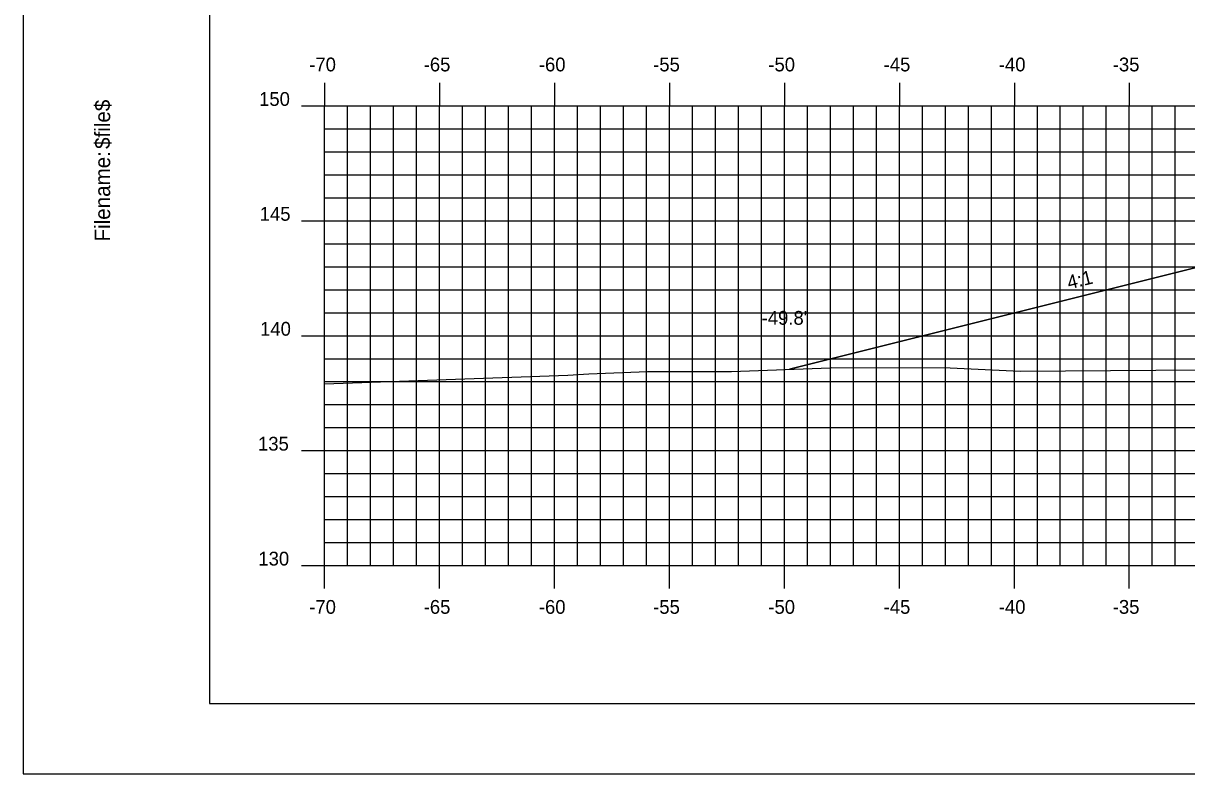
# Model space of a CAD drawing. Extents: x 851639 to 851810, y 365876 to 365986.
# Drawn here: x 851638.6 to 851689.2, y 365875.8 to 365908.4 of the extents above; entities that cross this region are included whole.
import ezdxf

# ---------------------------------------------------------------- set-up
doc = ezdxf.new("R2010")
doc.units = 0
for name, color, linetype in [('ANNOTATION', 7, 'Continuous'), ('BORDER', 7, 'Continuous'), ('D_Roadway_Centerline', 7, 'Continuous'), ('D_Roadway_SlopeLines', 7, 'Continuous'), ('D_Text_Standard', 7, 'Continuous'), ('H_V ANNOTATION', 7, 'Continuous'), ('MAJOR', 7, 'Continuous'), ('MINOR', 7, 'Continuous'), ('PLOT BOUNDARY', 7, 'Continuous'), ('S_Roadway_Centerline', 7, 'Continuous')]:
    doc.layers.add(name, color=color, linetype=linetype)

msp = doc.modelspace()

# ---------------------------------------------------------------- linework, layer by layer
at = {"layer": 'BORDER'}
msp.add_lwpolyline([(851646.655, 365878.833), (851806.655, 365878.833), (851806.655, 365983.833), (851646.655, 365983.833)], close=True, dxfattribs=at)
at = {"layer": 'D_Roadway_Centerline'}
msp.add_lwpolyline([(851671.874, 365893.373), (851687.655, 365897.318), (851697.655, 365899.818), (851721.655, 365898.522), (851731.655, 365896.022), (851745.471, 365892.568)], dxfattribs=at)
at = {"layer": 'D_Roadway_SlopeLines'}
msp.add_lwpolyline([(851697.655, 365899.818), (851687.655, 365897.318), (851671.874, 365893.373)], dxfattribs=at)
at = {"layer": 'MAJOR'}
for p, q in [((851651.655, 365905.835), (851651.655, 365904.833)), ((851656.655, 365905.835), (851656.655, 365904.833)), ((851661.655, 365905.835), (851661.655, 365904.833)), ((851666.655, 365905.835), (851666.655, 365904.833)), ((851671.655, 365905.835), (851671.655, 365904.833)), ((851676.655, 365905.835), (851676.655, 365904.833)), ((851681.655, 365905.835), (851681.655, 365904.833)), ((851686.655, 365905.835), (851686.655, 365904.833)), ((851650.653, 365904.833), (851651.655, 365904.833)), ((851651.655, 365904.833), (851791.655, 365904.833)), ((851651.655, 365884.833), (851651.655, 365904.833)), ((851651.655, 365884.833), (851651.655, 365904.833)), ((851651.655, 365904.833), (851791.655, 365904.833)), ((851656.655, 365884.833), (851656.655, 365904.833)), ((851661.655, 365884.833), (851661.655, 365904.833)), ((851666.655, 365884.833), (851666.655, 365904.833)), ((851671.655, 365884.833), (851671.655, 365904.833)), ((851676.655, 365884.833), (851676.655, 365904.833)), ((851681.655, 365884.833), (851681.655, 365904.833)), ((851686.655, 365884.833), (851686.655, 365904.833)), ((851650.653, 365899.833), (851651.655, 365899.833)), ((851651.655, 365899.833), (851791.655, 365899.833)), ((851650.653, 365894.833), (851651.655, 365894.833)), ((851651.655, 365894.833), (851791.655, 365894.833)), ((851650.653, 365889.833), (851651.655, 365889.833)), ((851651.655, 365889.833), (851791.655, 365889.833)), ((851650.653, 365884.833), (851651.655, 365884.833)), ((851651.655, 365884.833), (851791.655, 365884.833)), ((851651.655, 365884.833), (851791.655, 365884.833)), ((851651.655, 365883.831), (851651.655, 365884.833)), ((851656.655, 365883.831), (851656.655, 365884.833)), ((851661.655, 365883.831), (851661.655, 365884.833)), ((851666.655, 365883.831), (851666.655, 365884.833)), ((851671.655, 365883.831), (851671.655, 365884.833)), ((851676.655, 365883.831), (851676.655, 365884.833)), ((851681.655, 365883.831), (851681.655, 365884.833)), ((851686.655, 365883.831), (851686.655, 365884.833))]:
    msp.add_line(p, q, dxfattribs=at)
at = {"layer": 'MINOR'}
for p, q in [((851652.655, 365884.833), (851652.655, 365904.833)), ((851653.655, 365884.833), (851653.655, 365904.833)), ((851654.655, 365884.833), (851654.655, 365904.833)), ((851655.655, 365884.833), (851655.655, 365904.833)), ((851657.655, 365884.833), (851657.655, 365904.833)), ((851658.655, 365884.833), (851658.655, 365904.833)), ((851659.655, 365884.833), (851659.655, 365904.833)), ((851660.655, 365884.833), (851660.655, 365904.833)), ((851662.655, 365884.833), (851662.655, 365904.833)), ((851663.655, 365884.833), (851663.655, 365904.833)), ((851664.655, 365884.833), (851664.655, 365904.833)), ((851665.655, 365884.833), (851665.655, 365904.833)), ((851667.655, 365884.833), (851667.655, 365904.833)), ((851668.655, 365884.833), (851668.655, 365904.833)), ((851669.655, 365884.833), (851669.655, 365904.833)), ((851670.655, 365884.833), (851670.655, 365904.833)), ((851672.655, 365884.833), (851672.655, 365904.833)), ((851673.655, 365884.833), (851673.655, 365904.833)), ((851674.655, 365884.833), (851674.655, 365904.833)), ((851675.655, 365884.833), (851675.655, 365904.833)), ((851677.655, 365884.833), (851677.655, 365904.833)), ((851678.655, 365884.833), (851678.655, 365904.833)), ((851679.655, 365884.833), (851679.655, 365904.833)), ((851680.655, 365884.833), (851680.655, 365904.833)), ((851682.655, 365884.833), (851682.655, 365904.833)), ((851683.655, 365884.833), (851683.655, 365904.833)), ((851684.655, 365884.833), (851684.655, 365904.833)), ((851685.655, 365884.833), (851685.655, 365904.833)), ((851687.655, 365884.833), (851687.655, 365904.833)), ((851688.655, 365884.833), (851688.655, 365904.833)), ((851651.655, 365903.833), (851791.655, 365903.833)), ((851651.655, 365903.833), (851652.657, 365903.833)), ((851651.655, 365902.833), (851791.655, 365902.833)), ((851651.655, 365902.833), (851652.657, 365902.833)), ((851651.655, 365901.833), (851791.655, 365901.833)), ((851651.655, 365901.833), (851652.657, 365901.833)), ((851651.655, 365900.833), (851791.655, 365900.833)), ((851651.655, 365900.833), (851652.657, 365900.833)), ((851651.655, 365898.833), (851791.655, 365898.833)), ((851651.655, 365898.833), (851652.657, 365898.833)), ((851651.655, 365897.833), (851791.655, 365897.833)), ((851651.655, 365897.833), (851652.657, 365897.833)), ((851651.655, 365896.833), (851791.655, 365896.833)), ((851651.655, 365896.833), (851652.657, 365896.833)), ((851651.655, 365895.833), (851791.655, 365895.833)), ((851651.655, 365895.833), (851652.657, 365895.833)), ((851651.655, 365893.833), (851791.655, 365893.833)), ((851651.655, 365893.833), (851652.657, 365893.833)), ((851651.655, 365892.833), (851791.655, 365892.833)), ((851651.655, 365892.833), (851652.657, 365892.833)), ((851651.655, 365891.833), (851791.655, 365891.833)), ((851651.655, 365891.833), (851652.657, 365891.833)), ((851651.655, 365890.833), (851791.655, 365890.833)), ((851651.655, 365890.833), (851652.657, 365890.833)), ((851651.655, 365888.833), (851791.655, 365888.833)), ((851651.655, 365888.833), (851652.657, 365888.833)), ((851651.655, 365887.833), (851791.655, 365887.833)), ((851651.655, 365887.833), (851652.657, 365887.833)), ((851651.655, 365886.833), (851791.655, 365886.833)), ((851651.655, 365886.833), (851652.657, 365886.833)), ((851651.655, 365885.833), (851791.655, 365885.833)), ((851651.655, 365885.833), (851652.657, 365885.833))]:
    msp.add_line(p, q, dxfattribs=at)
at = {"layer": 'PLOT BOUNDARY'}
msp.add_lwpolyline([(851638.562, 365875.774), (851808.562, 365875.774), (851808.562, 365985.774), (851638.562, 365985.774)], close=True, dxfattribs=at)
at = {"layer": 'S_Roadway_Centerline'}
msp.add_lwpolyline([(851651.655, 365892.733), (851662.235, 365893.118), (851663.147, 365893.17), (851665.705, 365893.279), (851669.359, 365893.281), (851673.643, 365893.437), (851673.705, 365893.453), (851678.861, 365893.43), (851681.907, 365893.287), (851699.598, 365893.427), (851700.467, 365893.433), (851700.542, 365893.452), (851701.031, 365893.434), (851714.216, 365893.233), (851716.404, 365892.925), (851717.299, 365893.001), (851721.258, 365893.02), (851721.746, 365892.928), (851733.393, 365892.465), (851735.836, 365892.322), (851742.245, 365892.534), (851749.65, 365892.612)], dxfattribs=at)

# ---------------------------------------------------------------- texts
at = {"layer": 'ANNOTATION'}
msp.add_text('4:1', height=0.6, rotation=14.0362, dxfattribs=at).set_placement((851684.032, 365896.843))
at = {"layer": 'BORDER'}
for s, p in [('$file$', (851642.34, 365902.959)), ('Filename:', (851642.34, 365898.932))]:
    msp.add_text(s, height=0.6696, rotation=90, dxfattribs=at).set_placement(p)
at = {"layer": 'D_Text_Standard'}
msp.add_text("-49.8'", height=0.6, dxfattribs=at).set_placement((851670.668, 365895.309))
at = {"layer": 'H_V ANNOTATION'}
for s, p in [('-70', (851650.997, 365906.333)), ('-65', (851655.973, 365906.333)), ('-60', (851660.981, 365906.333)), ('-55', (851665.951, 365906.333)), ('-50', (851670.959, 365906.333)), ('-45', (851675.973, 365906.333)), ('-40', (851680.981, 365906.333)), ('-35', (851685.935, 365906.333)), ('150', (851648.817, 365904.833)), ('145', (851648.844, 365899.833)), ('140', (851648.86, 365894.833)), ('135', (851648.769, 365889.833)), ('130', (851648.785, 365884.833)), ('-70', (851650.997, 365882.733)), ('-65', (851655.973, 365882.733)), ('-60', (851660.981, 365882.733)), ('-55', (851665.951, 365882.733)), ('-50', (851670.959, 365882.733)), ('-45', (851675.973, 365882.733)), ('-40', (851680.981, 365882.733)), ('-35', (851685.935, 365882.733))]:
    msp.add_text(s, height=0.6, dxfattribs=at).set_placement(p)
at = {"layer": 'MAJOR'}
msp.add_text('-', height=0.006, dxfattribs=at).set_placement((851651.65, 365884.833))

doc.saveas('drawing.dxf')
